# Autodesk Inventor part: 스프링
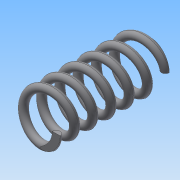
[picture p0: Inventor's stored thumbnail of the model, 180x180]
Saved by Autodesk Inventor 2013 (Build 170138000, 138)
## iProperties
Created: 2015-12
Part Number: 스프링
Material: 일반
Document SubType Name: Modeling
Designer: Administrator
Density: 1 g/cm^3
Mass: -0.0309104 g
Surface Area: 28.4714 cm^2
Volume: -0.0309104 cm^3
Author: Administrator
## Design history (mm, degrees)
sketch "스케치1"
  geometry: L1 (0, 0)-(0, 42); L2 (0, 42)-(8, 42); L3 (0, 0)-(8, 0); C1 r 1.5 at (8, 0)
  constraints: 6 end point, 1 centre point, 1 coincident, 1 parallel, 1 perpendicular, 1 vertical
  dimensions: "d0" = 42 distance of L1.start L1.end (derived); "d1" = 8 distance of L1.end L2.end; "d2" = 8 distance of L1.start L3.end; "d3" = 3 diameter of C1
feature "코일1" sketch "스케치1" pitch "d4" = 10; turns "d6" = 6; dims "d5" = 42 (= d0), "d7" = 0, angle "d8" = 90 deg, angle "d9" = 90 deg, "d10" = 0, "d11" = 0
sketch "스케치2"
  geometry: L1 (0, 12.5)-(42, 12.5); L2 (42, 12.5)-(42, -12.5); L3 (42, -12.5)-(0, -12.5); L4 (0, -12.5)-(0, 12.5); 2 further points
  constraints: 8 end point, 2 parallel, 1 coincident, 1 horizontal, 1 midpoint, 1 perpendicular
  dimensions: "d12" = 42 distance of L1.start L1.end (derived); "d14" = 25 distance of L1.end L2.end
extrude "돌출1" sketch "스케치2" stored distance "d15" = 10; taper "d16" = 0 deg
node "솔리드1"
